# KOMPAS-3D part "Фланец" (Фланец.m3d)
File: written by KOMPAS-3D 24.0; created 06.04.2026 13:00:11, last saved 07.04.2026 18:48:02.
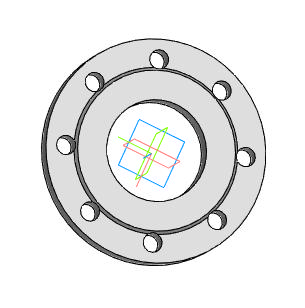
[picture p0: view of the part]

Document properties: Автор: R2D2; Полное имя файла: E:\Работа\Зайцев\Солянка\VSR1-13V-PED-F Клапан запорно-регулирующий DN.ru\DN100\исходные материалы\Фланец.m3d

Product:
- Component [standard]: (unnamed)  | qty 1  | Материал: ВЧ40 ГОСТ 7293-85 (density 7200 kg/m3); Масса: 4.73; additional columns: 100-16-01-2-B-ВЧ40-II-dв 116; Фланец; ГОСТ 33259-2015
- Part/product: Фланец
    Масса: 4.457556

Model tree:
1. Эскиз:8
2. Элемент выдавливания:8
     Расстояние 2 = 22
3. Эскиз:10  (with: Грань.Элемент выдавливания:8, Ребро.Элемент выдавливания:8)
4. Элемент выдавливания:12
5. Массив по концентрической сетке:1  (with: Элемент выдавливания:12, Эскиз:10)  (8 pattern instances)
     Шаг 2 = 360

Expressions: v520+50
Referenced files in C:\Program Files\ASCON\KOMPAS-3D v24\Libs\PolynomLib\DATA\vault\Methods\Kompas\3D\: PLib_Flange_GOST_33259_1401.m3d
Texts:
  BOSimple***Material:38d6725a-5efe-48e1-b177-a7817acb862a
  BOSimple***PART:fb490061-995a-84eb-4176-45574f06635f***SHORTLOC:B6A6_23E38AE8DB154823[II;2;Круглый;100;16;116;0;ВЧ40 ГОСТ 7293-85]
  Ch34
  Плоскость XY.Начало координат
  Ось Z.Начало координат
  Plane ZX. Origin
  Плоскость ZX.Начало координат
